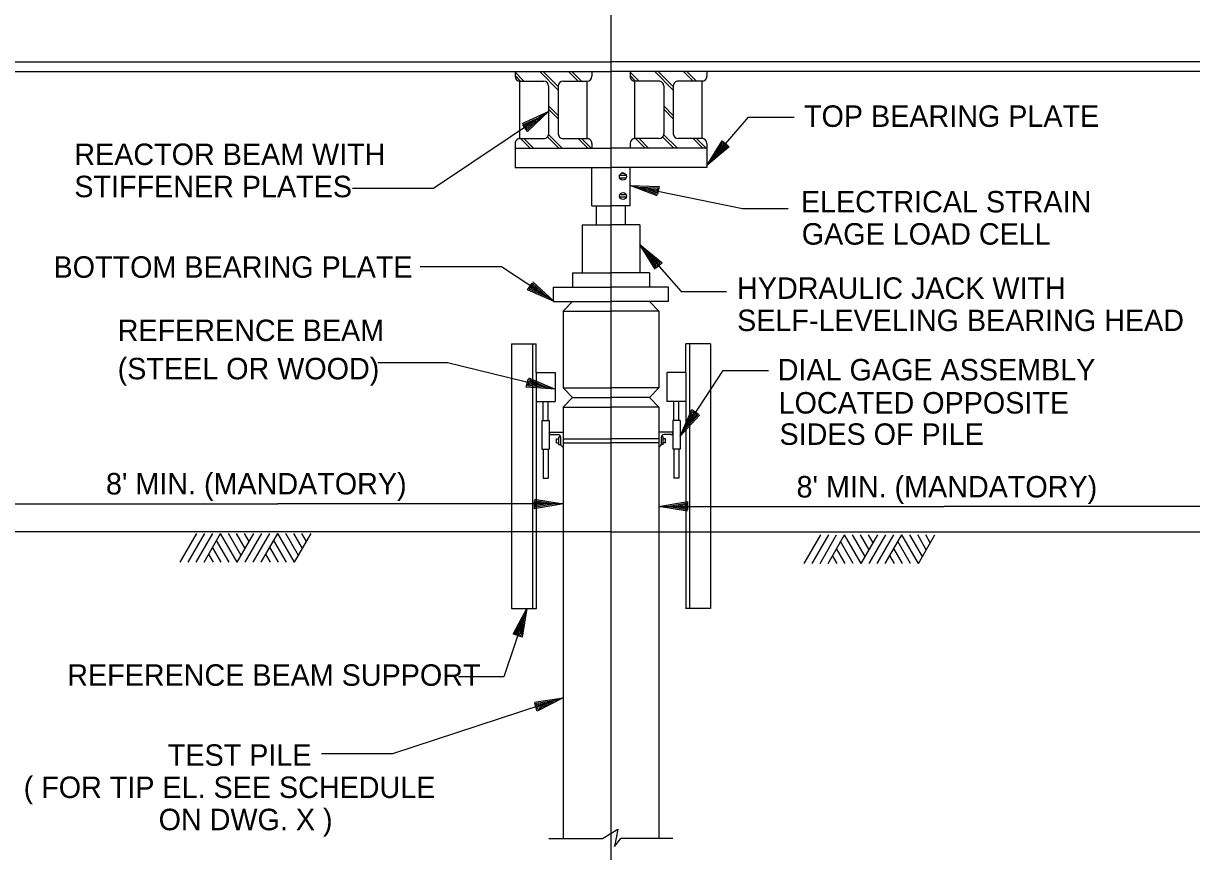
# Model space of a CAD drawing. Extents: x 22378.6 to 22422.6, y 22377.7 to 22411.7.
# Drawn here: x 22385.54 to 22393.16, y 22383.66 to 22389.06 of the extents above; entities that cross this region are included whole.
import ezdxf

# ---------------------------------------------------------------- set-up
doc = ezdxf.new("R2010")
doc.units = 0
for name, color, linetype in [('Level 1', 7, 'Continuous'), ('Level 2', 7, 'Continuous'), ('Level 3', 7, 'Continuous'), ('Level 4', 7, 'Continuous'), ('Level 7', 7, 'Continuous')]:
    doc.layers.add(name, color=color, linetype=linetype)

msp = doc.modelspace()

# ---------------------------------------------------------------- linework, layer by layer
at = {"layer": 'Level 1'}
for p, q in [((22389.3753, 22393.2465), (22389.3753, 22383.2487)), ((22388.8081, 22388.6857), (22388.7502, 22388.7436)), ((22388.786, 22388.6857), (22388.7502, 22388.7215)), ((22388.7503, 22388.7482), (22388.7503, 22388.717)), ((22389.0315, 22388.6277), (22388.911, 22388.7482)), ((22389.0315, 22388.6498), (22388.9331, 22388.7482)), ((22389.161, 22388.6857), (22389.0985, 22388.7482)), ((22389.183, 22388.6857), (22389.1205, 22388.7482)), ((22389.2503, 22388.7482), (22389.2503, 22388.717)), ((22389.5581, 22388.6857), (22389.5002, 22388.7436)), ((22389.536, 22388.6857), (22389.5002, 22388.7215)), ((22389.5003, 22388.7482), (22389.5003, 22388.717)), ((22389.7815, 22388.6277), (22389.661, 22388.7482)), ((22389.7815, 22388.6498), (22389.6831, 22388.7482)), ((22389.911, 22388.6857), (22389.8485, 22388.7482)), ((22389.933, 22388.6857), (22389.8705, 22388.7482)), ((22390.0003, 22388.7482), (22390.0003, 22388.717)), ((22388.7815, 22388.6857), (22388.9378, 22388.6857)), ((22388.969, 22388.6545), (22388.969, 22388.342)), ((22389.0315, 22388.6545), (22389.0315, 22388.342)), ((22389.0628, 22388.6857), (22389.219, 22388.6857)), ((22389.6878, 22388.6857), (22389.5315, 22388.6857)), ((22389.719, 22388.6545), (22389.719, 22388.342)), ((22389.7815, 22388.6545), (22389.7815, 22388.342)), ((22389.969, 22388.6857), (22389.8128, 22388.6857)), ((22389.0315, 22388.4623), (22388.969, 22388.5248)), ((22389.0315, 22388.4402), (22388.969, 22388.5027)), ((22388.969, 22388.4865), (22388.969, 22388.4865)), ((22389.7815, 22388.4623), (22389.719, 22388.5248)), ((22389.7815, 22388.4402), (22389.719, 22388.5027)), ((22388.9258, 22388.4577), (22388.9258, 22388.4577)), ((22389.036, 22388.2482), (22388.9618, 22388.3225)), ((22389.058, 22388.2482), (22388.968, 22388.3383)), ((22389.786, 22388.2482), (22389.7117, 22388.3226)), ((22389.808, 22388.2482), (22389.7183, 22388.338)), ((22388.7815, 22388.3107), (22388.9378, 22388.3107)), ((22388.8485, 22388.2482), (22388.786, 22388.3107)), ((22388.8705, 22388.2482), (22388.808, 22388.3107)), ((22389.0628, 22388.3107), (22389.219, 22388.3107)), ((22389.2235, 22388.2482), (22389.161, 22388.3107)), ((22389.2455, 22388.2482), (22389.1831, 22388.3107)), ((22389.2503, 22388.2795), (22389.2503, 22388.2482)), ((22389.5003, 22388.2795), (22389.5003, 22388.2482)), ((22389.6878, 22388.3107), (22389.5315, 22388.3107)), ((22389.5985, 22388.2482), (22389.536, 22388.3107)), ((22389.6205, 22388.2482), (22389.5581, 22388.3107)), ((22389.969, 22388.3107), (22389.8128, 22388.3107)), ((22389.9735, 22388.2482), (22389.911, 22388.3108)), ((22389.9955, 22388.2482), (22389.933, 22388.3108)), ((22390.0003, 22388.2795), (22390.0003, 22388.2482)), ((22390.0343, 22388.1749), (22390.0343, 22388.1749)), ((22390.0003, 22388.1355), (22390.0003, 22388.1355)), ((22389.5003, 22388.0055), (22389.5003, 22388.0055)), ((22389.5513, 22387.9951), (22389.5513, 22387.9951)), ((22389.5628, 22387.6211), (22389.5628, 22387.6211)), ((22389.5971, 22387.582), (22389.5971, 22387.582)), ((22388.9616, 22387.2768), (22388.9616, 22387.2768)), ((22389.005, 22387.2482), (22389.005, 22387.2482)), ((22389.0628, 22387.1857), (22389.3753, 22387.1857)), ((22389.6878, 22387.1857), (22389.3753, 22387.1857)), ((22388.9612, 22386.6888), (22388.9612, 22386.6888)), ((22389.0117, 22386.6764), (22389.0117, 22386.6764)), ((22389.0628, 22386.6857), (22389.3753, 22386.6857)), ((22389.6878, 22386.6857), (22389.3753, 22386.6857)), ((22389.0628, 22386.5607), (22389.3753, 22386.5607)), ((22389.6878, 22386.5607), (22389.3753, 22386.5607)), ((22389.8541, 22386.4139), (22389.8541, 22386.4139)), ((22388.969, 22386.3967), (22388.969, 22386.3967)), ((22388.9718, 22386.3967), (22389.0628, 22386.3967)), ((22388.9846, 22386.3811), (22389.0315, 22386.3811)), ((22389.0352, 22386.3154), (22389.0352, 22386.3658)), ((22389.0352, 22386.3658), (22389.0471, 22386.3658)), ((22389.0471, 22386.3654), (22389.0471, 22386.3186)), ((22389.7787, 22386.3967), (22389.6878, 22386.3967)), ((22389.7153, 22386.3658), (22389.7034, 22386.3658)), ((22389.7034, 22386.3654), (22389.7034, 22386.3186)), ((22389.7153, 22386.3154), (22389.7153, 22386.3658)), ((22389.7659, 22386.3811), (22389.719, 22386.3811)), ((22389.7815, 22386.3967), (22389.7815, 22386.3967)), ((22389.8256, 22386.3704), (22389.8256, 22386.3704)), ((22389.0342, 22386.3156), (22389.0463, 22386.3156)), ((22389.7164, 22386.3156), (22389.7042, 22386.3156)), ((22385.3441, 22385.9291), (22387.2034, 22385.9291)), ((22389.0628, 22385.9291), (22387.2034, 22385.9291)), ((22389.0108, 22385.9291), (22389.0108, 22385.9291)), ((22389.0628, 22385.9291), (22389.0628, 22385.9291)), ((22389.6878, 22385.9134), (22391.5471, 22385.9134)), ((22389.6878, 22385.9134), (22389.6878, 22385.9134)), ((22389.7398, 22385.9134), (22389.7398, 22385.9134)), ((22393.4065, 22385.9134), (22391.5471, 22385.9134)), ((22386.5665, 22385.5488), (22386.6747, 22385.7363)), ((22386.6185, 22385.5488), (22386.7267, 22385.7363)), ((22386.6705, 22385.5488), (22386.7787, 22385.7363)), ((22386.7223, 22385.5488), (22386.8306, 22385.7363)), ((22386.9388, 22385.5488), (22386.8306, 22385.7363)), ((22386.9648, 22385.5938), (22386.8826, 22385.7363)), ((22386.9908, 22385.6388), (22386.9346, 22385.7363)), ((22386.9388, 22385.5488), (22387.0471, 22385.7361)), ((22387.0168, 22385.6838), (22386.9866, 22385.7363)), ((22386.9908, 22385.5488), (22387.0992, 22385.7363)), ((22387.0427, 22385.5488), (22387.1511, 22385.7363)), ((22387.0947, 22385.5488), (22387.2031, 22385.7363)), ((22387.3113, 22385.5488), (22387.2031, 22385.7363)), ((22387.3373, 22385.5938), (22387.2551, 22385.7363)), ((22387.3633, 22385.6388), (22387.3071, 22385.7363)), ((22387.3113, 22385.5488), (22387.4197, 22385.7363)), ((22387.3893, 22385.6838), (22387.3591, 22385.7363)), ((22390.6341, 22385.5407), (22390.7424, 22385.7282)), ((22390.6861, 22385.5407), (22390.7944, 22385.7282)), ((22390.7381, 22385.5407), (22390.8464, 22385.7282)), ((22390.79, 22385.5407), (22390.8982, 22385.7282)), ((22391.0065, 22385.5407), (22390.8982, 22385.7282)), ((22391.0325, 22385.5857), (22390.9502, 22385.7282)), ((22391.0585, 22385.6307), (22391.0022, 22385.7282)), ((22391.0065, 22385.5407), (22391.1147, 22385.7281)), ((22391.0845, 22385.6757), (22391.0542, 22385.7282)), ((22391.0585, 22385.5407), (22391.1669, 22385.7282)), ((22391.1104, 22385.5407), (22391.2187, 22385.7282)), ((22391.1624, 22385.5407), (22391.2707, 22385.7282)), ((22391.379, 22385.5407), (22391.2707, 22385.7282)), ((22391.405, 22385.5857), (22391.3227, 22385.7282)), ((22391.431, 22385.6307), (22391.3747, 22385.7282)), ((22391.379, 22385.5407), (22391.4874, 22385.7282)), ((22391.457, 22385.6757), (22391.4267, 22385.7282)), ((22386.8868, 22385.5488), (22386.8046, 22385.6913)), ((22387.2593, 22385.5488), (22387.1771, 22385.6913)), ((22390.9545, 22385.5407), (22390.8722, 22385.6832)), ((22391.327, 22385.5407), (22391.2447, 22385.6832)), ((22386.783, 22385.5488), (22386.7527, 22385.6013)), ((22386.8348, 22385.5488), (22386.7786, 22385.6463)), ((22387.1555, 22385.5488), (22387.1252, 22385.6013)), ((22387.2073, 22385.5488), (22387.1511, 22385.6463)), ((22390.8506, 22385.5407), (22390.8204, 22385.5932)), ((22390.9025, 22385.5407), (22390.8462, 22385.6382)), ((22391.2231, 22385.5407), (22391.1929, 22385.5932)), ((22391.275, 22385.5407), (22391.2187, 22385.6382)), ((22388.8097, 22385.1989), (22388.8097, 22385.1989)), ((22388.826, 22385.2482), (22388.826, 22385.2482)), ((22389.0628, 22384.666), (22389.0628, 22384.666)), ((22389.0135, 22384.6497), (22389.0135, 22384.6497))]:
    msp.add_line(p, q, dxfattribs=at)
for points in [[(22388.969, 22388.4865), (22388.2177, 22387.9853), (22387.6896, 22387.9853)], [(22388.7963, 22388.4085), (22388.969, 22388.4865), (22388.8307, 22388.3569), (22388.8013, 22388.401), (22388.9258, 22388.4577), (22388.8318, 22388.3697), (22388.8129, 22388.398), (22388.8842, 22388.4299), (22388.8329, 22388.3825), (22388.8251, 22388.3941), (22388.8409, 22388.4011)], [(22390.0003, 22388.1355), (22390.2722, 22388.4505), (22390.5686, 22388.4505)], [(22390.146, 22388.2568), (22390.0003, 22388.1355), (22390.0991, 22388.2973), (22390.1392, 22388.2627), (22390.0343, 22388.1749), (22390.1014, 22388.2847), (22390.1271, 22388.2625), (22390.067, 22388.2127), (22390.1037, 22388.2721), (22390.1144, 22388.263), (22390.101, 22388.2521)], [(22389.5003, 22388.0055), (22390.2332, 22387.8562), (22390.5296, 22387.8562)], [(22389.6774, 22387.9378), (22389.5003, 22388.0055), (22389.6898, 22387.9985), (22389.6792, 22387.9466), (22389.5513, 22387.9951), (22389.6799, 22387.9903), (22389.6731, 22387.957), (22389.6003, 22387.9851), (22389.6701, 22387.9821), (22389.6673, 22387.9684), (22389.6512, 22387.9747)], [(22389.5628, 22387.6211), (22389.8318, 22387.3144), (22390.1281, 22387.3144)], [(22389.6629, 22387.4601), (22389.5628, 22387.6211), (22389.7095, 22387.5009), (22389.6696, 22387.466), (22389.5971, 22387.582), (22389.6967, 22387.5004), (22389.6711, 22387.4779), (22389.6301, 22387.5444), (22389.6839, 22387.4998), (22389.6734, 22387.4906), (22389.6644, 22387.5053)], [(22389.005, 22387.2482), (22388.661, 22387.4741), (22388.1316, 22387.4741)], [(22388.8657, 22387.3768), (22389.005, 22387.2482), (22388.8317, 22387.325), (22388.8608, 22387.3693), (22388.9616, 22387.2768), (22388.8439, 22387.3289), (22388.8625, 22387.3573), (22388.9198, 22387.3042), (22388.8561, 22387.3329), (22388.8637, 22387.3446), (22388.8763, 22387.3328)], [(22389.0117, 22386.6764), (22388.31, 22386.8487), (22387.8564, 22386.8487)], [(22389.8256, 22386.3704), (22390.1058, 22386.799), (22390.4021, 22386.799)], [(22388.8375, 22386.7511), (22389.0117, 22386.6764), (22388.8227, 22386.6909), (22388.8354, 22386.7424), (22388.9612, 22386.6888), (22388.8329, 22386.6987), (22388.841, 22386.7317), (22388.9127, 22386.7007), (22388.8431, 22386.7065), (22388.8464, 22386.7201), (22388.8622, 22386.7131)], [(22389.9539, 22386.5099), (22389.8256, 22386.3704), (22389.902, 22386.5439), (22389.9464, 22386.5149), (22389.8541, 22386.4139), (22389.906, 22386.5317), (22389.9345, 22386.5131), (22389.8814, 22386.4557), (22389.91, 22386.5195), (22389.9217, 22386.5119), (22389.9099, 22386.4993)], [(22388.8758, 22385.9601), (22389.0628, 22385.9291), (22388.8758, 22385.8981), (22388.8758, 22385.9511), (22389.0108, 22385.9291), (22388.8838, 22385.9081), (22388.8838, 22385.9421), (22388.9608, 22385.9291), (22388.8918, 22385.9181), (22388.8918, 22385.9321), (22388.9088, 22385.9291)], [(22389.8748, 22385.8824), (22389.6878, 22385.9134), (22389.8748, 22385.9444), (22389.8748, 22385.8914), (22389.7398, 22385.9134), (22389.8668, 22385.9344), (22389.8668, 22385.9004), (22389.7898, 22385.9134), (22389.8588, 22385.9244), (22389.8588, 22385.9104), (22389.8418, 22385.9134)], [(22388.826, 22385.2482), (22388.6778, 22384.8014), (22388.3815, 22384.8014)], [(22388.7377, 22385.0805), (22388.826, 22385.2482), (22388.7966, 22385.061), (22388.7463, 22385.0777), (22388.8097, 22385.1989), (22388.7896, 22385.0717), (22388.7574, 22385.0824), (22388.7939, 22385.1514), (22388.7827, 22385.0825), (22388.7694, 22385.0869), (22388.7776, 22385.1021)], [(22389.0628, 22384.666), (22387.9506, 22384.2991), (22387.488, 22384.2991)], [(22388.8755, 22384.6369), (22389.0628, 22384.666), (22388.895, 22384.578), (22388.8784, 22384.6283), (22389.0135, 22384.6497), (22388.8994, 22384.59), (22388.8888, 22384.6223), (22388.966, 22384.6341), (22388.9039, 22384.602), (22388.8995, 22384.6153), (22388.9166, 22384.6178)]]:
    msp.add_lwpolyline(points, dxfattribs=at)
for centre, radius, start, end in [((22388.7816, 22388.717), 0.0313, 180.05353, 269.8509), ((22389.219, 22388.7171), 0.0313, 270.05571, 359.84888), ((22389.5315, 22388.7169), 0.0311, 179.79253, 270.11189), ((22389.9691, 22388.717), 0.0312, 269.82774, 0.07684), ((22388.9377, 22388.6545), 0.0313, 0.08614, 89.81828), ((22389.0629, 22388.6544), 0.0313, 90.05579, 179.8488), ((22389.6879, 22388.6546), 0.0312, 359.85773, 90.04669), ((22389.8128, 22388.6545), 0.0312, 89.86032, 180.04426), ((22388.9379, 22388.3419), 0.0312, 269.92074, 0.17483), ((22389.0627, 22388.342), 0.0312, 179.92315, 270.17226), ((22389.6878, 22388.342), 0.0313, 270.14909, 359.94647), ((22389.8129, 22388.3421), 0.0313, 180.11856, 269.97684), ((22388.7815, 22388.2796), 0.0312, 89.92066, 180.1749), ((22389.2191, 22388.2795), 0.0312, 359.95573, 90.13968), ((22389.5316, 22388.2795), 0.0313, 90.18171, 179.91386), ((22389.969, 22388.2794), 0.0314, 0.18377, 89.91164), ((22388.9846, 22386.3967), 0.0156, 214.98711, 270.0317), ((22389.0315, 22386.3654), 0.0156, 0.02086, 89.86443), ((22389.7191, 22386.3654), 0.0156, 90.16262, 179.91382), ((22389.766, 22386.3967), 0.0156, 269.93014, 325.01285), ((22389.0627, 22386.3185), 0.0156, 179.82563, 270.47914), ((22389.6878, 22386.3186), 0.0156, 270.13556, 359.97913)]:
    msp.add_arc(centre, radius, start, end, dxfattribs=at)
at = {"layer": 'Level 2'}
for p, q in [((22384.3753, 22388.8107), (22389.3753, 22388.8107)), ((22394.3753, 22388.8107), (22389.3753, 22388.8107)), ((22388.7815, 22388.3107), (22388.7815, 22388.6857)), ((22389.219, 22388.3107), (22389.219, 22388.6857)), ((22389.5315, 22388.3107), (22389.5315, 22388.6857)), ((22389.969, 22388.3107), (22389.969, 22388.6857)), ((22389.4751, 22388.0695), (22389.4315, 22388.0695)), ((22389.474, 22388.0539), (22389.432, 22388.0539)), ((22389.4586, 22388.0852), (22389.4425, 22388.0852)), ((22389.4755, 22387.9445), (22389.4324, 22387.9445)), ((22389.4761, 22387.9289), (22389.4325, 22387.9289)), ((22388.7267, 22386.973), (22388.7267, 22385.7482)), ((22388.7267, 22386.973), (22388.8867, 22386.973)), ((22388.8627, 22386.973), (22388.8627, 22385.2482)), ((22388.8867, 22386.7855), (22388.8867, 22386.973)), ((22390.0238, 22386.973), (22389.8638, 22386.973)), ((22389.8638, 22386.7855), (22389.8638, 22386.973)), ((22389.8878, 22386.973), (22389.8878, 22385.2482)), ((22390.0238, 22386.973), (22390.0238, 22385.7482)), ((22388.8867, 22386.7855), (22389.0117, 22386.7855)), ((22388.8867, 22386.7855), (22388.8867, 22386.598)), ((22389.0117, 22386.7855), (22389.0117, 22386.598)), ((22389.8638, 22386.7855), (22389.7388, 22386.7855)), ((22389.7388, 22386.7855), (22389.7388, 22386.598)), ((22389.8638, 22386.7855), (22389.8638, 22386.598)), ((22388.8867, 22386.598), (22389.0117, 22386.598)), ((22388.8867, 22386.598), (22388.8867, 22385.7482)), ((22388.9336, 22386.473), (22388.9336, 22386.598)), ((22388.9648, 22386.473), (22388.9648, 22386.598)), ((22389.8638, 22386.598), (22389.7388, 22386.598)), ((22389.7857, 22386.473), (22389.7857, 22386.598)), ((22389.8169, 22386.473), (22389.8169, 22386.598)), ((22389.8638, 22386.598), (22389.8638, 22385.7482)), ((22388.925, 22386.473), (22388.925, 22386.2855)), ((22388.925, 22386.473), (22388.9718, 22386.473)), ((22388.9718, 22386.473), (22388.9718, 22386.2855)), ((22389.7787, 22386.473), (22389.7787, 22386.2855)), ((22389.8256, 22386.473), (22389.7787, 22386.473)), ((22389.8256, 22386.473), (22389.8256, 22386.2855)), ((22389.0194, 22386.3541), (22389.0352, 22386.3541)), ((22389.0194, 22386.3264), (22389.0194, 22386.3541)), ((22389.0628, 22386.3541), (22389.3753, 22386.3541)), ((22389.6878, 22386.3541), (22389.3753, 22386.3541)), ((22389.7311, 22386.3541), (22389.7153, 22386.3541)), ((22389.7311, 22386.3264), (22389.7311, 22386.3541)), ((22388.925, 22386.2855), (22388.9718, 22386.2855)), ((22388.9336, 22386.2855), (22388.9336, 22386.098)), ((22388.9648, 22386.2855), (22388.9648, 22386.098)), ((22389.0194, 22386.3264), (22389.0352, 22386.3264)), ((22389.0628, 22386.3264), (22389.3753, 22386.3264)), ((22389.6878, 22386.3264), (22389.3753, 22386.3264)), ((22389.7311, 22386.3264), (22389.7153, 22386.3264)), ((22389.8256, 22386.2855), (22389.7787, 22386.2855)), ((22389.7857, 22386.2855), (22389.7857, 22386.098)), ((22389.8169, 22386.2855), (22389.8169, 22386.098)), ((22388.9336, 22386.098), (22388.9648, 22386.098)), ((22389.8169, 22386.098), (22389.7857, 22386.098)), ((22389.3753, 22385.7482), (22381.8102, 22385.7482)), ((22388.7267, 22385.7482), (22388.7267, 22385.2482)), ((22388.8867, 22385.7482), (22388.8867, 22385.2482)), ((22389.0628, 22385.7482), (22389.0628, 22383.7482)), ((22389.3753, 22385.7482), (22396.9404, 22385.7482)), ((22389.6878, 22385.7482), (22389.6878, 22383.7482)), ((22389.8638, 22385.7482), (22389.8638, 22385.2482)), ((22390.0238, 22385.7482), (22390.0238, 22385.2482)), ((22388.7267, 22385.2482), (22388.8898, 22385.2482)), ((22390.0238, 22385.2482), (22389.8607, 22385.2482)), ((22388.9711, 22383.7482), (22389.321, 22383.7482)), ((22389.321, 22383.7482), (22389.4194, 22383.8098)), ((22389.4194, 22383.8098), (22389.3974, 22383.6956)), ((22389.3974, 22383.6956), (22389.4404, 22383.7482)), ((22389.7794, 22383.7482), (22389.4404, 22383.7482))]:
    msp.add_line(p, q, dxfattribs=at)
for centre in [(22389.453, 22388.0633), (22389.4541, 22387.9362)]:
    msp.add_circle(centre, 0.023, dxfattribs=at)
at = {"layer": 'Level 3'}
msp.add_line((22388.7503, 22388.2795), (22388.7503, 22388.2482), dxfattribs=at)
at = {"layer": 'Level 7'}
for p, q in [((22384.3753, 22388.7482), (22389.3753, 22388.7482)), ((22394.3753, 22388.7482), (22389.3753, 22388.7482)), ((22388.7503, 22388.2482), (22389.3753, 22388.2482)), ((22388.7503, 22388.2482), (22388.7503, 22388.1232)), ((22390.0003, 22388.2482), (22389.3753, 22388.2482)), ((22390.0003, 22388.2482), (22390.0003, 22388.1232)), ((22388.7503, 22388.1232), (22389.3753, 22388.1232)), ((22389.2503, 22387.8732), (22389.2503, 22388.1232)), ((22390.0003, 22388.1232), (22389.3753, 22388.1232)), ((22389.5003, 22387.8732), (22389.5003, 22388.1232)), ((22389.2503, 22387.8732), (22389.3753, 22387.8732)), ((22389.2815, 22387.7482), (22389.2815, 22387.8732)), ((22389.5003, 22387.8732), (22389.3753, 22387.8732)), ((22389.469, 22387.7482), (22389.469, 22387.8732)), ((22389.1878, 22387.7482), (22389.3753, 22387.7482)), ((22389.1878, 22387.7482), (22389.1878, 22387.4357)), ((22389.5628, 22387.7482), (22389.3753, 22387.7482)), ((22389.5628, 22387.7482), (22389.5628, 22387.4357)), ((22389.1253, 22387.4357), (22389.3753, 22387.4357)), ((22389.1253, 22387.4357), (22389.1253, 22387.342)), ((22389.6253, 22387.4357), (22389.3753, 22387.4357)), ((22389.6253, 22387.4357), (22389.6253, 22387.342)), ((22389.0003, 22387.342), (22389.3753, 22387.342)), ((22389.0003, 22387.2482), (22389.0003, 22387.342)), ((22389.7503, 22387.342), (22389.3753, 22387.342)), ((22389.7503, 22387.2482), (22389.7503, 22387.342)), ((22389.0003, 22387.2482), (22389.3753, 22387.2482)), ((22389.0628, 22387.1857), (22389.1253, 22387.2482)), ((22389.7503, 22387.2482), (22389.3753, 22387.2482)), ((22389.6878, 22387.1857), (22389.6253, 22387.2482)), ((22389.0628, 22387.1857), (22389.0628, 22386.6857)), ((22389.6878, 22387.1857), (22389.6878, 22386.6857)), ((22389.0628, 22386.6857), (22389.1253, 22386.6232)), ((22389.6878, 22386.6857), (22389.6253, 22386.6232)), ((22389.0628, 22386.5607), (22389.1253, 22386.6232)), ((22389.1253, 22386.6232), (22389.3753, 22386.6232)), ((22389.6253, 22386.6232), (22389.3753, 22386.6232)), ((22389.6878, 22386.5607), (22389.6253, 22386.6232)), ((22389.0628, 22386.5607), (22389.0628, 22385.7482)), ((22389.6878, 22386.5607), (22389.6878, 22385.7482))]:
    msp.add_line(p, q, dxfattribs=at)

# ---------------------------------------------------------------- texts
at = {"layer": 'Level 4'}
for s, p in [('TOP BEARING PLATE', (22390.6335, 22388.3873)), ('REACTOR BEAM WITH', (22385.8768, 22388.1386)), ('STIFFENER PLATES', (22385.8768, 22387.9286)), ('ELECTRICAL STRAIN', (22390.613, 22387.8295)), ('GAGE LOAD CELL', (22390.6189, 22387.6195)), ('BOTTOM BEARING PLATE', (22385.7412, 22387.4036)), ('HYDRAULIC JACK WITH', (22390.1974, 22387.2661)), ('SELF-LEVELING BEARING HEAD', (22390.1974, 22387.0561)), ('REFERENCE BEAM', (22386.1593, 22386.9908)), ('(STEEL OR WOOD)', (22386.1593, 22386.7414)), ('DIAL GAGE ASSEMBLY', (22390.4622, 22386.7341)), ('LOCATED OPPOSITE', (22390.468, 22386.5183)), ('SIDES OF PILE', (22390.4738, 22386.3142)), ("8' MIN. (MANDATORY)", (22386.083, 22385.9909)), ("8' MIN. (MANDATORY)", (22390.5849, 22385.9711)), ('REFERENCE BEAM SUPPORT', (22385.8306, 22384.7435)), ('TEST PILE', (22386.4865, 22384.2219)), ('( FOR TIP EL. SEE SCHEDULE', (22385.5465, 22384.0119)), ('ON DWG. X )', (22386.4265, 22383.8019))]:
    msp.add_text(s, height=0.14, dxfattribs=at).set_placement(p)

doc.saveas('drawing.dxf')
